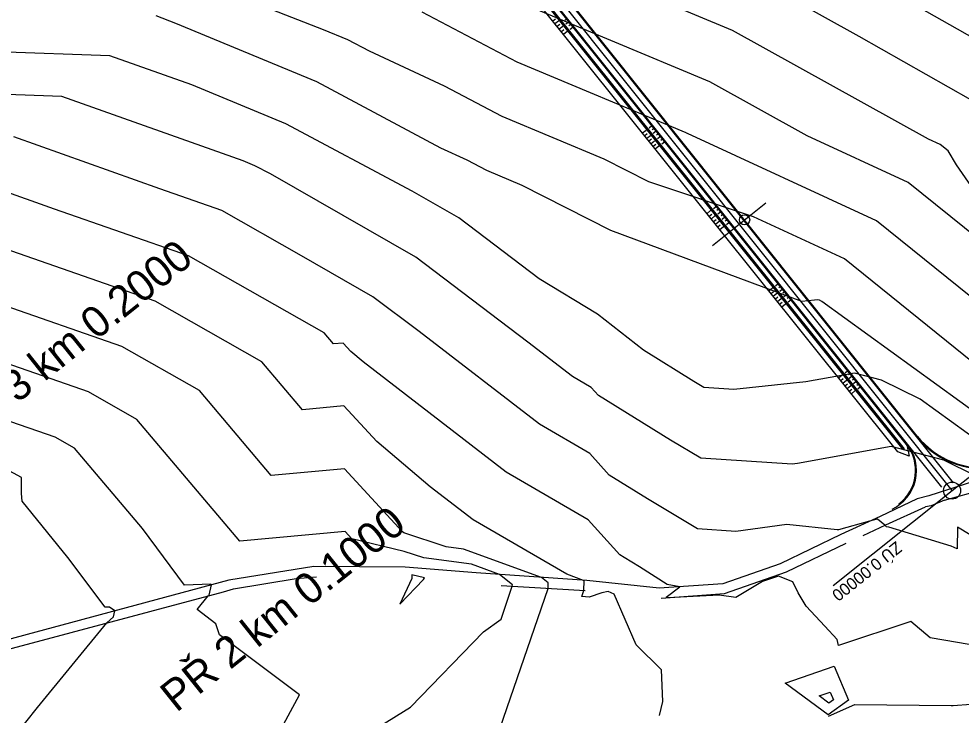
# Model space of a CAD drawing. Extents: x -549238 to -546764, y -1036895 to -1033794.
# Drawn here: x -548178.9 to -547902.6, y -1035504.2 to -1035300.1 of the extents above; entities that cross this region are included whole.
import ezdxf

# ---------------------------------------------------------------- set-up
doc = ezdxf.new("R2010")
doc.units = 0
for name, color, linetype in [('hlavni_vrst', 7, 'Continuous'), ('hrana_L', 7, 'Continuous'), ('norm_vrst', 7, 'Continuous'), ('POLYGONY_SITUACE_PO', 7, 'Continuous'), ('u_prikop_C12', 7, 'Continuous'), ('u_sirka_1_5m', 7, 'Continuous'), ('x_navrh_C12', 7, 'Continuous'), ('x_osa_C12', 7, 'Continuous'), ('x_popis_oblouky_C12', 7, 'Continuous'), ('x_popis_pricne_rezy_C12', 7, 'Continuous')]:
    doc.layers.add(name, color=color, linetype=linetype)

msp = doc.modelspace()

# ---------------------------------------------------------------- linework, layer by layer
at = {"layer": 'hlavni_vrst'}
for p, q in [((-547969.61, -1035303.43), (-548019.52, -1035282.69)), ((-547912.21, -1035335.29), (-547969.61, -1035303.43)), ((-548152.18, -1035310.9), (-548239.54, -1035307.83)), ((-548128.21, -1035319.42), (-548152.18, -1035310.9)), ((-548100.61, -1035330.81), (-548128.21, -1035319.42)), ((-548063.57, -1035350.62), (-548100.61, -1035330.81)), ((-547908.8, -1035336.87), (-547912.21, -1035335.29)), ((-547906.45, -1035338.77), (-547908.8, -1035336.87)), ((-547903.97, -1035342.87), (-547906.45, -1035338.77)), ((-547852.38, -1035417.8), (-547903.97, -1035342.87)), ((-548049.94, -1035358.43), (-548063.57, -1035350.62)), ((-548026.31, -1035376.32), (-548049.94, -1035358.43)), ((-548148.73, -1035396.14), (-548210.36, -1035374.64)), ((-548009.25, -1035386.63), (-548026.31, -1035376.32)), ((-547995.73, -1035397.25), (-548009.25, -1035386.63)), ((-548125.97, -1035409.06), (-548148.73, -1035396.14)), ((-547980.98, -1035406.38), (-547995.73, -1035397.25)), ((-547933.91, -1035403.95), (-547948.12, -1035406.53)), ((-547925.95, -1035405.99), (-547933.91, -1035403.95)), ((-547978.09, -1035408.12), (-547980.98, -1035406.38)), ((-547948.12, -1035406.53), (-547969.28, -1035408.7)), ((-547914.62, -1035411.6), (-547925.95, -1035405.99)), ((-548104.95, -1035433.96), (-548125.97, -1035409.06)), ((-547969.28, -1035408.7), (-547978.09, -1035408.12)), ((-547888.14, -1035430.83), (-547914.62, -1035411.6)), ((-548083.44, -1035431.99), (-548104.95, -1035433.96)), ((-548066.37, -1035450.47), (-548083.44, -1035431.99)), ((-548066.01, -1035450.77), (-548066.37, -1035450.47)), ((-548053.6, -1035454.84), (-548066.01, -1035450.77)), ((-548048.53, -1035455.53), (-548053.6, -1035454.84)), ((-548025.63, -1035463.85), (-548048.53, -1035455.53)), ((-548023.69, -1035465.43), (-548025.63, -1035463.85)), ((-548023.71, -1035467.04), (-548023.69, -1035465.43)), ((-548037.74, -1035507.93), (-548023.71, -1035467.04))]:
    msp.add_line(p, q, dxfattribs=at)
at = {"layer": 'hrana_L'}
for p, q in [((-547894.45, -1035434.25), (-547912.1, -1035439.94)), ((-547907.45, -1035441.23), (-547893.45, -1035437.29)), ((-547915.47, -1035440.79), (-547926.36, -1035445.93)), ((-547912.1, -1035439.94), (-547915.47, -1035440.79)), ((-547924.71, -1035448.39), (-547913.07, -1035443.16)), ((-547911.38, -1035442.82), (-547913.07, -1035443.16)), ((-547907.45, -1035441.23), (-547911.38, -1035442.82)), ((-547926.36, -1035445.93), (-547937.9, -1035451.29)), ((-547931.36, -1035451.58), (-547924.71, -1035448.39)), ((-547937.9, -1035451.29), (-547955.7, -1035459.9)), ((-547953.79, -1035462.21), (-547936.33, -1035453.75)), ((-547955.7, -1035459.9), (-547972.5, -1035465.74)), ((-548092.43, -1035460.6), (-548117.3, -1035464.61)), ((-548065.59, -1035460.83), (-548092.43, -1035460.6)), ((-548044.85, -1035462.5), (-548065.59, -1035460.83)), ((-548012.33, -1035464.78), (-548044.85, -1035462.5)), ((-547972.01, -1035468.6), (-547953.79, -1035462.21)), ((-548117.3, -1035464.61), (-548191.5, -1035484.65)), ((-548115.99, -1035467.23), (-548097.61, -1035464.2)), ((-548097.61, -1035464.2), (-548091.63, -1035463.63)), ((-547991.14, -1035467), (-548012.33, -1035464.78)), ((-547972.5, -1035465.74), (-547991.14, -1035467)), ((-548189.89, -1035486.99), (-548118.94, -1035468.07)), ((-548118.94, -1035468.07), (-548115.99, -1035467.23)), ((-548037.46, -1035466.21), (-548012.89, -1035467.69)), ((-547990.56, -1035469.94), (-547972.01, -1035468.6))]:
    msp.add_line(p, q, dxfattribs=at)
at = {"layer": 'norm_vrst'}
for p, q in [((-547890.77, -1035310.38), (-547951.66, -1035275.88)), ((-548089.6, -1035303.24), (-548127.49, -1035288.48)), ((-547932.49, -1035305.23), (-547962.88, -1035288.36)), ((-548005.35, -1035306.45), (-548028.33, -1035296.81)), ((-548132.83, -1035301.46), (-548138.61, -1035299.21)), ((-548032.78, -1035312.73), (-548060.62, -1035298.12)), ((-548091.52, -1035318.5), (-548132.83, -1035301.46)), ((-548082.43, -1035306.19), (-548089.6, -1035303.24)), ((-547899.77, -1035323.76), (-547932.49, -1035305.23)), ((-548076.12, -1035309.57), (-548082.43, -1035306.19)), ((-547976.33, -1035318.51), (-548005.35, -1035306.45)), ((-548054.06, -1035319.81), (-548076.12, -1035309.57)), ((-547983.23, -1035333.52), (-548032.78, -1035312.73)), ((-548055.14, -1035337.96), (-548091.52, -1035318.5)), ((-547947.78, -1035334.36), (-547976.33, -1035318.51)), ((-548166.28, -1035322.8), (-548251.77, -1035319.8)), ((-548037.23, -1035328.65), (-548054.06, -1035319.81)), ((-548113.09, -1035341.72), (-548166.28, -1035322.8)), ((-548007.26, -1035341.22), (-548037.23, -1035328.65)), ((-548137.55, -1035349.93), (-548180.38, -1035334.7)), ((-547983.1, -1035333.58), (-547983.23, -1035333.52)), ((-547982.8, -1035333.68), (-547983.1, -1035333.58)), ((-547927.45, -1035359.27), (-547982.8, -1035333.68)), ((-547918.13, -1035348.07), (-547947.78, -1035334.36)), ((-548047.5, -1035341.5), (-548055.14, -1035337.96)), ((-548109.7, -1035343.12), (-548113.09, -1035341.72)), ((-548041.67, -1035344.56), (-548047.5, -1035341.5)), ((-547994.23, -1035347.86), (-548007.26, -1035341.22)), ((-548105.15, -1035345.55), (-548109.7, -1035343.12)), ((-548168.45, -1035355.86), (-548194.49, -1035346.6)), ((-548062.5, -1035369.98), (-548105.15, -1035345.55)), ((-548031.29, -1035348.92), (-548041.67, -1035344.56)), ((-548119.38, -1035356.27), (-548137.55, -1035349.93)), ((-548005.35, -1035362.14), (-548031.29, -1035348.92)), ((-547963.45, -1035358.14), (-547994.23, -1035347.86)), ((-547897.66, -1035364.59), (-547918.13, -1035348.07)), ((-548129.17, -1035369.56), (-548168.45, -1035355.86)), ((-548096.03, -1035369.52), (-548119.38, -1035356.27)), ((-547936.78, -1035370.47), (-547963.45, -1035358.14)), ((-547888.86, -1035390.42), (-547927.45, -1035359.27)), ((-548138.95, -1035382.85), (-548199.35, -1035361.78)), ((-548005.35, -1035362.14), (-548005.35, -1035362.14)), ((-547949.34, -1035382.95), (-548005.35, -1035362.14)), ((-548005.35, -1035362.14), (-548005.35, -1035362.14)), ((-548005.35, -1035362.14), (-548005.35, -1035362.14)), ((-548089.36, -1035392.15), (-548129.17, -1035369.56)), ((-548075.07, -1035381.53), (-548096.03, -1035369.52)), ((-548029.66, -1035394.85), (-548062.5, -1035369.98)), ((-547880.07, -1035416.24), (-547936.78, -1035370.47)), ((-548107.67, -1035400.6), (-548138.95, -1035382.85)), ((-548061.55, -1035391.77), (-548075.07, -1035381.53)), ((-547945.62, -1035382.57), (-547949.34, -1035382.95)), ((-547944.7, -1035382.4), (-547945.62, -1035382.57)), ((-547944.17, -1035382.53), (-547944.7, -1035382.4)), ((-547943.43, -1035382.9), (-547944.17, -1035382.53)), ((-547880.7, -1035428.46), (-547943.43, -1035382.9)), ((-548086.62, -1035395.39), (-548089.36, -1035392.15)), ((-548026.29, -1035418.94), (-548061.55, -1035391.77)), ((-548158.51, -1035409.43), (-548197.06, -1035395.99)), ((-548083.81, -1035395.14), (-548086.62, -1035395.39)), ((-548081.59, -1035397.55), (-548083.81, -1035395.14)), ((-548016.58, -1035404.93), (-548029.66, -1035394.85)), ((-548077.98, -1035400.6), (-548081.59, -1035397.55)), ((-548095.78, -1035414.68), (-548107.67, -1035400.6)), ((-548036, -1035432.95), (-548077.98, -1035400.6)), ((-548011.1, -1035408.12), (-548016.58, -1035404.93)), ((-548178.13, -1035434.53), (-548224.26, -1035409.65)), ((-548144.28, -1035417.51), (-548158.51, -1035409.43)), ((-548008.99, -1035410.46), (-548011.1, -1035408.12)), ((-547987.79, -1035423.59), (-548008.99, -1035410.46)), ((-548083.63, -1035413.56), (-548095.78, -1035414.68)), ((-548073.98, -1035424.01), (-548083.63, -1035413.56)), ((-548168.3, -1035422.73), (-548183.76, -1035417.33)), ((-548114.11, -1035453.24), (-548144.28, -1035417.51)), ((-548011.52, -1035427.52), (-548026.29, -1035418.94)), ((-548162.59, -1035425.97), (-548168.3, -1035422.73)), ((-548058.33, -1035437.23), (-548073.98, -1035424.01)), ((-547978.98, -1035428.86), (-547987.79, -1035423.59)), ((-548142.69, -1035449.53), (-548162.59, -1035425.97)), ((-547923.13, -1035425.49), (-547950.62, -1035430.48)), ((-547907.73, -1035429.45), (-547923.13, -1035425.49)), ((-548005.84, -1035433.84), (-548011.52, -1035427.52)), ((-547952.19, -1035430.64), (-547978.98, -1035428.86)), ((-547898.37, -1035434.08), (-547907.73, -1035429.45)), ((-547950.62, -1035430.48), (-547952.19, -1035430.64)), ((-548178.12, -1035439.25), (-548178.13, -1035434.53)), ((-548011.94, -1035446.93), (-548036, -1035432.95)), ((-547994.59, -1035440.8), (-548005.84, -1035433.84)), ((-548045.71, -1035446.96), (-548058.33, -1035437.23)), ((-548177.95, -1035441.52), (-548178.12, -1035439.25)), ((-547979.87, -1035449.61), (-547994.59, -1035440.8)), ((-548164.55, -1035457.95), (-548177.95, -1035441.52)), ((-548018.22, -1035462.93), (-548045.71, -1035446.96)), ((-548002.69, -1035457.21), (-548011.94, -1035446.93)), ((-547953.77, -1035448.32), (-547968.72, -1035450.35)), ((-547938.93, -1035449.9), (-547953.77, -1035448.32)), ((-547929.47, -1035447.37), (-547938.57, -1035449.84)), ((-547927.12, -1035446.79), (-547929.47, -1035447.37)), ((-547925.03, -1035448.55), (-547927.12, -1035446.79)), ((-547924.46, -1035449.04), (-547925.03, -1035448.55)), ((-547923.86, -1035449.14), (-547924.46, -1035449.04)), ((-547905.57, -1035454.63), (-547923.86, -1035449.14)), ((-547903.68, -1035449.13), (-547903.78, -1035455.43)), ((-547884.61, -1035460.69), (-547903.68, -1035449.13)), ((-548130.34, -1035466.12), (-548142.69, -1035449.53)), ((-548083.25, -1035450.41), (-548114.11, -1035453.24)), ((-548081.26, -1035452.57), (-548083.25, -1035450.41)), ((-547968.72, -1035450.35), (-547979.87, -1035449.61)), ((-547938.57, -1035449.84), (-547938.93, -1035449.9)), ((-548065.91, -1035456.19), (-548081.26, -1035452.57)), ((-547903.78, -1035455.43), (-547905.57, -1035454.63)), ((-548060.11, -1035458.09), (-548065.91, -1035456.19)), ((-548001.4, -1035458.01), (-548002.69, -1035457.21)), ((-548153.64, -1035472.6), (-548164.55, -1035457.95)), ((-548046.17, -1035460), (-548060.11, -1035458.09)), ((-548037.95, -1035462.98), (-548046.17, -1035460)), ((-547996.91, -1035460.69), (-548001.4, -1035458.01)), ((-548060, -1035464), (-548063.7, -1035463.12)), ((-548063.7, -1035463.12), (-548063.68, -1035464.11)), ((-548034.2, -1035466.02), (-548037.95, -1035462.98)), ((-548013.32, -1035464.71), (-548018.22, -1035462.93)), ((-547988.82, -1035465.93), (-547996.91, -1035460.69)), ((-548122.65, -1035465.82), (-548130.34, -1035466.12)), ((-548123.14, -1035469.03), (-548122.4, -1035465.99)), ((-548122.4, -1035465.99), (-548122.65, -1035465.82)), ((-548063.68, -1035464.11), (-548067.21, -1035471.66)), ((-548067.21, -1035471.66), (-548060.26, -1035464.43)), ((-548060.26, -1035464.43), (-548060, -1035464)), ((-548034.21, -1035466.41), (-548034.2, -1035466.02)), ((-548013.17, -1035464.83), (-548013.32, -1035464.71)), ((-548013.21, -1035467.67), (-548013.17, -1035464.83)), ((-547985.11, -1035466.59), (-547988.82, -1035465.93)), ((-547960.89, -1035465.04), (-547968.71, -1035469.77)), ((-547956.16, -1035463.44), (-547960.89, -1035465.04)), ((-547952, -1035465.1), (-547956.16, -1035463.44)), ((-547950.42, -1035468.35), (-547952, -1035465.1)), ((-548037.53, -1035476.08), (-548034.21, -1035466.41)), ((-548013.8, -1035469.41), (-548013.21, -1035467.67)), ((-548007.92, -1035468.32), (-548011.64, -1035469.61)), ((-548006.15, -1035467.95), (-548007.92, -1035468.32)), ((-548004.31, -1035468.7), (-548006.15, -1035467.95)), ((-548004.33, -1035468.76), (-548004.31, -1035468.7)), ((-547997.86, -1035483.64), (-548004.33, -1035468.76)), ((-547989.12, -1035469.6), (-547985.11, -1035466.59)), ((-547948.01, -1035472.3), (-547950.42, -1035468.35)), ((-548126.64, -1035473.22), (-548123.39, -1035469.26)), ((-548123.39, -1035469.26), (-548123.14, -1035469.03)), ((-548011.64, -1035469.61), (-548013.8, -1035469.41)), ((-547988.71, -1035469.81), (-547989.12, -1035469.6)), ((-547973.56, -1035469.05), (-547988.71, -1035469.81)), ((-547968.71, -1035469.77), (-547973.56, -1035469.05)), ((-548152.36, -1035472.55), (-548153.64, -1035472.6)), ((-548150.72, -1035473.64), (-548152.36, -1035472.55)), ((-548151.16, -1035475.43), (-548150.72, -1035473.64)), ((-548121.16, -1035477.49), (-548126.64, -1035473.22)), ((-547942.62, -1035478.12), (-547948.01, -1035472.3)), ((-548153.08, -1035477.17), (-548151.16, -1035475.43)), ((-548042.66, -1035479.8), (-548037.53, -1035476.08)), ((-547917.35, -1035476.78), (-547938.59, -1035483.78)), ((-547911.72, -1035481.6), (-547917.35, -1035476.78)), ((-548173.43, -1035501.96), (-548153.08, -1035477.17)), ((-548120.09, -1035480.68), (-548121.16, -1035477.49)), ((-548064.07, -1035501.86), (-548042.66, -1035479.8)), ((-547939, -1035482.08), (-547942.62, -1035478.12)), ((-548096.64, -1035498.3), (-548120.09, -1035480.68)), ((-547938.59, -1035483.78), (-547939, -1035482.08)), ((-547892.53, -1035484.87), (-547911.72, -1035481.6)), ((-547990.46, -1035490.94), (-547997.86, -1035483.64)), ((-547954.25, -1035494.86), (-547939.88, -1035489.82)), ((-547939.88, -1035489.82), (-547935.68, -1035499.84)), ((-547990.11, -1035500.23), (-547990.46, -1035490.94)), ((-547941.63, -1035504.16), (-547954.25, -1035494.86)), ((-548105.45, -1035514.49), (-548096.64, -1035498.3)), ((-547944.22, -1035498.58), (-547940.99, -1035497.45)), ((-547941.38, -1035500.67), (-547944.22, -1035498.58)), ((-547940.99, -1035497.45), (-547940.04, -1035499.7)), ((-548188.67, -1035521), (-548173.43, -1035501.96)), ((-548073.07, -1035507.45), (-548064.07, -1035501.86)), ((-547991.06, -1035504.34), (-547990.11, -1035500.23)), ((-547935.68, -1035499.84), (-547941.63, -1035504.16)), ((-547941.54, -1035504.56), (-547933.82, -1035501.13)), ((-547940.04, -1035499.7), (-547941.38, -1035500.67)), ((-547933.82, -1035501.13), (-547905.57, -1035501.43)), ((-547905.57, -1035501.43), (-547904.93, -1035501.36)), ((-547904.93, -1035501.36), (-547899.77, -1035501.03))]:
    msp.add_line(p, q, dxfattribs=at)
at = {"layer": 'POLYGONY_SITUACE_PO'}
msp.add_circle((-547905.27, -1035438.39), 2.5, dxfattribs=at)
at = {"layer": 'u_prikop_C12'}
for p, q in [((-547919.57, -1035426.37), (-548208.81, -1035065.18)), ((-547919.27, -1035426.11), (-548208.49, -1035064.94)), ((-547921.14, -1035427.06), (-548210.54, -1035065.56)), ((-548022.32, -1035300.66), (-548021.57, -1035300.06)), ((-548018.26, -1035300.11), (-548018.85, -1035300.58)), ((-548021.7, -1035301.44), (-548020.65, -1035300.6)), ((-548021.07, -1035302.22), (-548020.32, -1035301.62)), ((-548020.45, -1035303), (-548019.4, -1035302.16)), ((-548017.64, -1035300.89), (-548018.55, -1035301.62)), ((-548017.01, -1035301.67), (-548017.61, -1035302.15)), ((-548016.39, -1035302.45), (-548017.3, -1035303.18)), ((-548019.82, -1035303.78), (-548019.08, -1035303.19)), ((-548019.2, -1035304.57), (-548018.14, -1035303.72)), ((-547996.03, -1035333.51), (-547994.99, -1035332.67)), ((-547993.26, -1035331.42), (-547994.13, -1035332.12)), ((-547992.63, -1035332.2), (-547993.17, -1035332.64)), ((-547992.01, -1035332.99), (-547992.88, -1035333.68)), ((-547995.4, -1035334.29), (-547994.65, -1035333.69)), ((-547994.78, -1035335.07), (-547993.73, -1035334.23)), ((-547994.15, -1035335.85), (-547993.4, -1035335.25)), ((-547993.53, -1035336.63), (-547992.48, -1035335.79)), ((-547991.38, -1035333.77), (-547991.93, -1035334.2)), ((-547990.76, -1035334.55), (-547991.63, -1035335.24)), ((-547990.13, -1035335.33), (-547990.69, -1035335.77)), ((-547989.51, -1035336.11), (-547990.38, -1035336.81)), ((-547992.9, -1035337.41), (-547992.16, -1035336.81)), ((-547992.28, -1035338.19), (-547991.22, -1035337.34)), ((-547974.37, -1035355.07), (-547975.21, -1035355.75)), ((-547977.11, -1035357.13), (-547976.07, -1035356.3)), ((-547976.49, -1035357.91), (-547975.74, -1035357.31)), ((-547975.86, -1035358.69), (-547974.82, -1035357.85)), ((-547973.74, -1035355.85), (-547974.26, -1035356.26)), ((-547973.12, -1035356.63), (-547973.96, -1035357.31)), ((-547972.5, -1035357.42), (-547973.02, -1035357.83)), ((-547971.87, -1035358.2), (-547972.71, -1035358.87)), ((-547975.24, -1035359.48), (-547974.49, -1035358.88)), ((-547974.61, -1035360.26), (-547973.56, -1035359.41)), ((-547973.99, -1035361.04), (-547973.24, -1035360.44)), ((-547973.36, -1035361.82), (-547972.31, -1035360.97)), ((-547971.25, -1035358.98), (-547971.77, -1035359.4)), ((-547970.62, -1035359.76), (-547971.46, -1035360.43)), ((-547958.97, -1035379.8), (-547957.92, -1035378.97)), ((-547958.34, -1035380.58), (-547957.59, -1035379.98)), ((-547956.25, -1035377.76), (-547957.06, -1035378.42)), ((-547955.62, -1035378.55), (-547956.11, -1035378.93)), ((-547955, -1035379.33), (-547955.81, -1035379.98)), ((-547954.38, -1035380.11), (-547954.87, -1035380.5)), ((-547957.72, -1035381.36), (-547956.67, -1035380.53)), ((-547957.09, -1035382.15), (-547956.34, -1035381.55)), ((-547956.47, -1035382.93), (-547955.41, -1035382.08)), ((-547955.84, -1035383.71), (-547955.09, -1035383.11)), ((-547953.75, -1035380.89), (-547954.56, -1035381.54)), ((-547953.13, -1035381.67), (-547953.62, -1035382.07)), ((-547952.5, -1035382.45), (-547953.31, -1035383.1)), ((-547955.22, -1035384.49), (-547954.16, -1035383.64)), ((-547938.55, -1035405.31), (-547937.5, -1035404.47)), ((-547935.86, -1035403.29), (-547936.65, -1035403.92)), ((-547935.23, -1035404.08), (-547935.69, -1035404.44)), ((-547934.61, -1035404.86), (-547935.4, -1035405.49)), ((-547937.92, -1035406.09), (-547937.17, -1035405.49)), ((-547937.3, -1035406.87), (-547936.25, -1035406.03)), ((-547936.67, -1035407.65), (-547935.92, -1035407.05)), ((-547936.05, -1035408.43), (-547934.99, -1035407.59)), ((-547933.99, -1035405.64), (-547934.45, -1035406.01)), ((-547933.36, -1035406.42), (-547934.15, -1035407.05)), ((-547932.74, -1035407.2), (-547933.21, -1035407.58)), ((-547932.11, -1035407.98), (-547932.9, -1035408.61)), ((-547935.42, -1035409.21), (-547934.67, -1035408.61)), ((-547934.8, -1035409.99), (-547933.74, -1035409.15)), ((-547919.57, -1035426.37), (-547919.27, -1035426.11))]:
    msp.add_line(p, q, dxfattribs=at)
msp.add_lwpolyline([(-547918.57, -1035424.94), (-547917.82, -1035428.26), (-547921.14, -1035427.06)], dxfattribs=at)
at = {"layer": 'u_sirka_1_5m'}
msp.add_circle((-547966.11, -1035359), 1.5, dxfattribs=at)
at = {"layer": 'x_navrh_C12'}
for p, q in [((-547904.86, -1035436.1), (-548175.46, -1035097.26)), ((-547918.64, -1035424.86), (-548178.39, -1035099.6)), ((-547908.29, -1035437.41), (-548178.19, -1035099.44)), ((-547915.48, -1035422.41), (-548170.25, -1035103.38))]:
    msp.add_line(p, q, dxfattribs=at)
for centre, radius, start, end in [((-547896.14, -1035406.96), 25, 218.6103, 285.7841), ((-547896.14, -1035406.96), 24.75, 218.6103, 278.089), ((-547928.21, -1035432.5), 12.5, 295.4098, 38.6103), ((-547928.21, -1035432.5), 12.25, 306.9915, 38.6103)]:
    msp.add_arc(centre, radius, start, end, dxfattribs=at)
at = {"layer": 'x_osa_C12'}
msp.add_line((-547905.27, -1035438.39), (-548206.06, -1035061.74), dxfattribs=at)
at = {"layer": 'x_popis_oblouky_C12'}
msp.add_lwpolyline([(-547940.11, -1035466.2), (-547905.27, -1035438.39)], dxfattribs=at)
at = {"layer": 'x_popis_pricne_rezy_C12'}
for points in [[(-547975.49, -1035366.49), (-547967.68, -1035360.25), (-547959.86, -1035354.01)], [(-547913.09, -1035444.63), (-547905.27, -1035438.39), (-547897.46, -1035432.15)]]:
    msp.add_lwpolyline(points, dxfattribs=at)

# ---------------------------------------------------------------- texts
at = {"layer": 'x_popis_oblouky_C12'}
msp.add_text('ZÚ 0.00000', height=3.5, rotation=218.6103, dxfattribs=at).set_placement((-547921.73, -1035453.08))
at = {"layer": 'x_popis_pricne_rezy_C12'}
for s, p in [('PŘ 3 km 0.2000', (-548195.12, -1035425.5)), ('PŘ 2 km 0.1000', (-548132.71, -1035503.64))]:
    msp.add_text(s, height=9.0627, rotation=38.6103, dxfattribs=at).set_placement(p)

doc.saveas('drawing.dxf')
